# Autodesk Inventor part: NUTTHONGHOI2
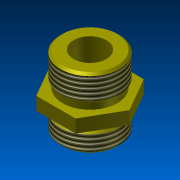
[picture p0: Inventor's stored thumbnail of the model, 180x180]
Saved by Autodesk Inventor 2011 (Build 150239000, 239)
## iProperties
Created: 2011-04
Part Number: NUTTHONGHOI2
Document SubType Name: Modeling
Designer: TRINH
Density: 1 g/cm^3
Mass: 13.7084 g
Surface Area: 57.8284 cm^2
Volume: 13.7084 cm^3
Author: TRINH
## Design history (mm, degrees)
sketch "Sketch1"
  geometry: C1 r 13.5 at (47.483, 48.152)
  constraints: 1 centre point
  dimensions: "d3" = 27 diameter of C1
extrude "Extrusion1" new body sketch "Sketch1" distance "d4" = 9; taper "d5" = 0 deg
sketch "Sketch2"
  geometry: C1 r 13.5 at (0, 0) reference; C2 r 12.5 at (0, 0); 1 further point
  constraints: 1 centre point, 1 coincident
  dimensions: "d6" = 25 diameter of C2
extrude "Extrusion2" join sketch "Sketch2" distance "d7" = 11; taper "d8" = 0 deg
sketch "Sketch4"
  geometry: C1 r 12.5 at (0, 0) reference; C2 r 13.5 at (0, 0); 1 further point
  constraints: 1 centre point, 1 coincident
  dimensions: "d10" = 27 diameter of C2
extrude "Extrusion3" join sketch "Sketch4" distance "d11" = 12; taper "d12" = 0 deg
workplane "Work Plane1"
sketch "Sketch5"
  geometry: L1 (18, 0)-(9, -15.588); L2 (9, -15.588)-(-9, -15.588); L3 (-9, -15.588)-(-18, 0); L4 (-18, 0)-(-9, 15.588); L5 (-9, 15.588)-(9, 15.588); L6 (9, 15.588)-(18, 0); C1 r 12.5 at (0, 0) reference; 2 further points
  constraints: 12 end point, 1 coincident, 13 other
  dimensions: "d14" = 36 distance of L3.end L1.start
extrude "Extrusion4" join sketch "Sketch5" distance "d15" = 6; taper "d16" = 0 deg
chamfer "Chamfer1" distance "d17" = 1; stored, may be unused: second distance "d18" = 2, angle "d19" = 45 deg
chamfer "Chamfer2" distance "d20" = 1; stored, may be unused: second distance "d21" = 2, angle "d22" = 45 deg
thread "Thread1" dims "d23" = 10, "d24" = 0
thread "Thread2" dims "d25" = 10, "d26" = 0
sketch "Sketch6"
  geometry: C1 r 12.5 at (0, 0) reference; C2 r 7.5 at (0, 0); 1 further point
  constraints: 1 centre point, 1 coincident
  dimensions: "d27" = 15 diameter of C2
extrude "Extrusion5" cut sketch "Sketch6" stored distance "d28" = 6; taper "d29" = 0 deg
body "Solid1"
other parameters: "d13" = -15
